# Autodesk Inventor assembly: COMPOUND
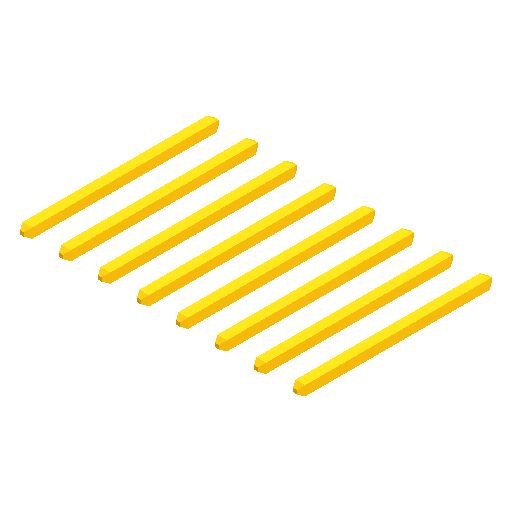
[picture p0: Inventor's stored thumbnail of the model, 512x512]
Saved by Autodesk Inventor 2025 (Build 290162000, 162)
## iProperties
Created: 2025-05
Part Number: COMPOUND
Document SubType Name: Assembly
Designer: R5800u
Author: R5800u
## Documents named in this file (9)
- C:\Users\R5800u\Desktop\drone\c3\ESP32-C3 Super Mini breakout expansion board module -Assembly\COMPOUND_4.iam
- C:\Users\R5800u\Desktop\drone\c3\ESP32-C3 Super Mini breakout expansion board module -Assembly\COMPOUND_32.ipt
- C:\Users\R5800u\Desktop\drone\c3\ESP32-C3 Super Mini breakout expansion board module -Assembly\COMPOUND_33.ipt
- C:\Users\R5800u\Desktop\drone\c3\ESP32-C3 Super Mini breakout expansion board module -Assembly\COMPOUND_34.ipt
- C:\Users\R5800u\Desktop\drone\c3\ESP32-C3 Super Mini breakout expansion board module -Assembly\COMPOUND_35.ipt
- C:\Users\R5800u\Desktop\drone\c3\ESP32-C3 Super Mini breakout expansion board module -Assembly\COMPOUND_36.ipt
- C:\Users\R5800u\Desktop\drone\c3\ESP32-C3 Super Mini breakout expansion board module -Assembly\COMPOUND_37.ipt
- C:\Users\R5800u\Desktop\drone\c3\ESP32-C3 Super Mini breakout expansion board module -Assembly\COMPOUND_38.ipt
- C:\Users\R5800u\Desktop\drone\c3\ESP32-C3 Super Mini breakout expansion board module -Assembly\COMPOUND_39.ipt
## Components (8 placed, 8 different names)
1. 40
2. 41
3. 42
4. 43
5. 44
6. 45
7. 46
8. 47
